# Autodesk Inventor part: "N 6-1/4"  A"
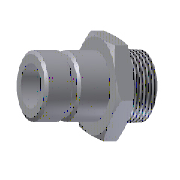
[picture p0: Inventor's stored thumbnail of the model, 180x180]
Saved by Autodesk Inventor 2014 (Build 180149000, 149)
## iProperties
IsCustomPart: 1
Created: 2009-11
Part Number: "N 6-1/4"  A"
Material: Copper,Cu
Description: Connector Plug
Document SubType Name: Modeling
Designer: gaom
Standard Revision: 1
Manufacturer: DME
Language: en-US
Size Designation: "N 6-1/4"  A"
Categories: <MemberInstance><Categories><Category DisplayName="Mold" InternalName="349578f2-f4d4-4954-8c09-8e99297a61c0" Mnemonic="MOLD"><Category DisplayName="Cooling Comp
Mass: 1.2815 g
Surface Area: 14.3289 cm^2
Volume: 1.2815 cm^3
Density: 8.96 g/cm^3
Appearance: Default
Author: gaom
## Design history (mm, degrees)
sketch "Sketch1"
  geometry: L1 (0, -11.81)-(0, 28.79) reference; L2 (36.525, 1.418)-(37.025, 17.418); L3 (37.025, 17.418)-(36.525, 17.418); L4 (36.525, 17.418)-(36.525, 1.418); L5 (6.391, -6.01)-(6.579, 0); L6 (6.391, -6.01)-(3, -6.01); L7 (6.579, 0)-(6.694, 3.7); L8 (3, -6.01)-(3, 22.99); L9 (4.7, 8.5)-(4.7, 22.99); L10 (4.7, 22.99)-(3, 22.99); L11 (4.7, 8.5)-(8, 8.5); L12 (6.694, 3.7)-(8, 3.7); L13 (8, 3.7)-(9.238, 4.415); L14 (9.238, 4.415)-(9.238, 7.785); L15 (9.238, 7.785)-(8, 8.5); 1 further point
  constraints: 28 end point, 3 horizontal, 3 vertical, 2 parallel, 2 perpendicular, 1 collinear, 1 equal length, 1 horizontal alignment
  dimensions: "d0" = 0.5 distance of L2.end L3.end (derived); "d2" = 16 distance of L3.end L2.start (derived); "d3" = 13.157 diameter of L5.end L1 (= R_); "d6" = 9.4 diameter of L9 L1 (= d1); "d7" = 6 diameter of L8 L1 (= d); "d10" = 29 distance between parallel lines of L6 L10 (= L); "d51" = 6.01 vertical distance of L5.start L5.end (= a); "d59" = 3.7 distance from line of L5.end L12 (derived); "d60" = 60 deg angle of L14 L15 (derived); "d61" = 60 deg angle of L14 L13 (derived); "d62" = 16 diameter of L11.end L1 (derived); "d63" = 18.47521 diameter of L14 L1 (derived); "d64" = 4.8 distance between parallel lines of L12 L11 (derived)
revolve "Revolution1" sketch "Sketch1" stored, may be unused: angle "d20" = 90 deg
sketch "Sketch2"
  geometry: L1 (0, -4.598)-(0, 27.588) reference; L2 (4.7, 8.5)-(4.7, 22.99) reference; L3 (4.7, 17.194)-(4.2, 16.694); L4 (4.2, 16.694)-(4.2, 15.694); L5 (4.2, 15.694)-(4.7, 15.194); L6 (4.7, 22.99)-(-4.7, 22.99) reference; L7 (4.7, 17.194)-(4.7, 15.194); 1 further point
  constraints: 8 end point, 2 point on line, 1 collinear, 1 perpendicular, 1 vertical
  dimensions: "d24" = 0.5 distance between parallel lines of L2 L4 (derived); "d25" = 2 distance of L5.end L3.start (derived); "d26" = 5.796 distance from line of L6 L3.start (derived); "d27" = 135 deg angle of L4 L3 (derived); "d55" = 14.49 distance of L2.start L2.end (derived)
revolve "Revolution2" sketch "Sketch2" stored, may be unused: angle "d28" = 90 deg
thread "Thread1" dims "d29" = 10, "d30" = 0
chamfer "Chamfer1" distance "d36" = 0.5; stored, may be unused: second distance "d37" = 2, angle "d38" = 45 deg
body "Solid1"
sketch "Sketch3"
  geometry: L1 (-12.933, 0)-(12.933, 0) reference; L2 (9.238, 0)-(4.619, -8); L3 (4.619, -8)-(-4.619, -8); L4 (-4.619, -8)-(-9.238, 0); L5 (-9.238, 0)-(-4.619, 8); L6 (-4.619, 8)-(4.619, 8); L7 (4.619, 8)-(9.238, 0); 2 further points
  constraints: 12 end point, 1 coincident, 1 point on line, 13 other
  dimensions: "d65" = 16 distance between parallel lines of L4 L7 (derived)
extrude "Extrusion1" sketch "Sketch3" stored distance "d66" = 10; taper "d67" = 0 deg
other parameters: "R_" = 13.157 [user parameter; used in 1 equation term], "d1" = 9.4 [user parameter; used in 1 equation term], "d" = 6 [user parameter; used in 1 equation term], "L" = 29 [user parameter; used in 1 equation term], "SW" = 16 [user parameter], "A_" = 26 [user parameter], "H_" = 19 [user parameter], "a" = 6.01 [user parameter; used in 1 equation term], "f_" = 3.7 [user parameter], "d53" = 0, "d68" = 0, "d69" = 3.7 (derived), "d100" = 0.5 [user parameter], "d101" = 16 [user parameter], "d102" = 2 [user parameter], "d103" = 135 deg [user parameter], "d104" = 60 deg [user parameter], "L2" = 9.71 [user parameter], "L1" = 14.49 [user parameter]
